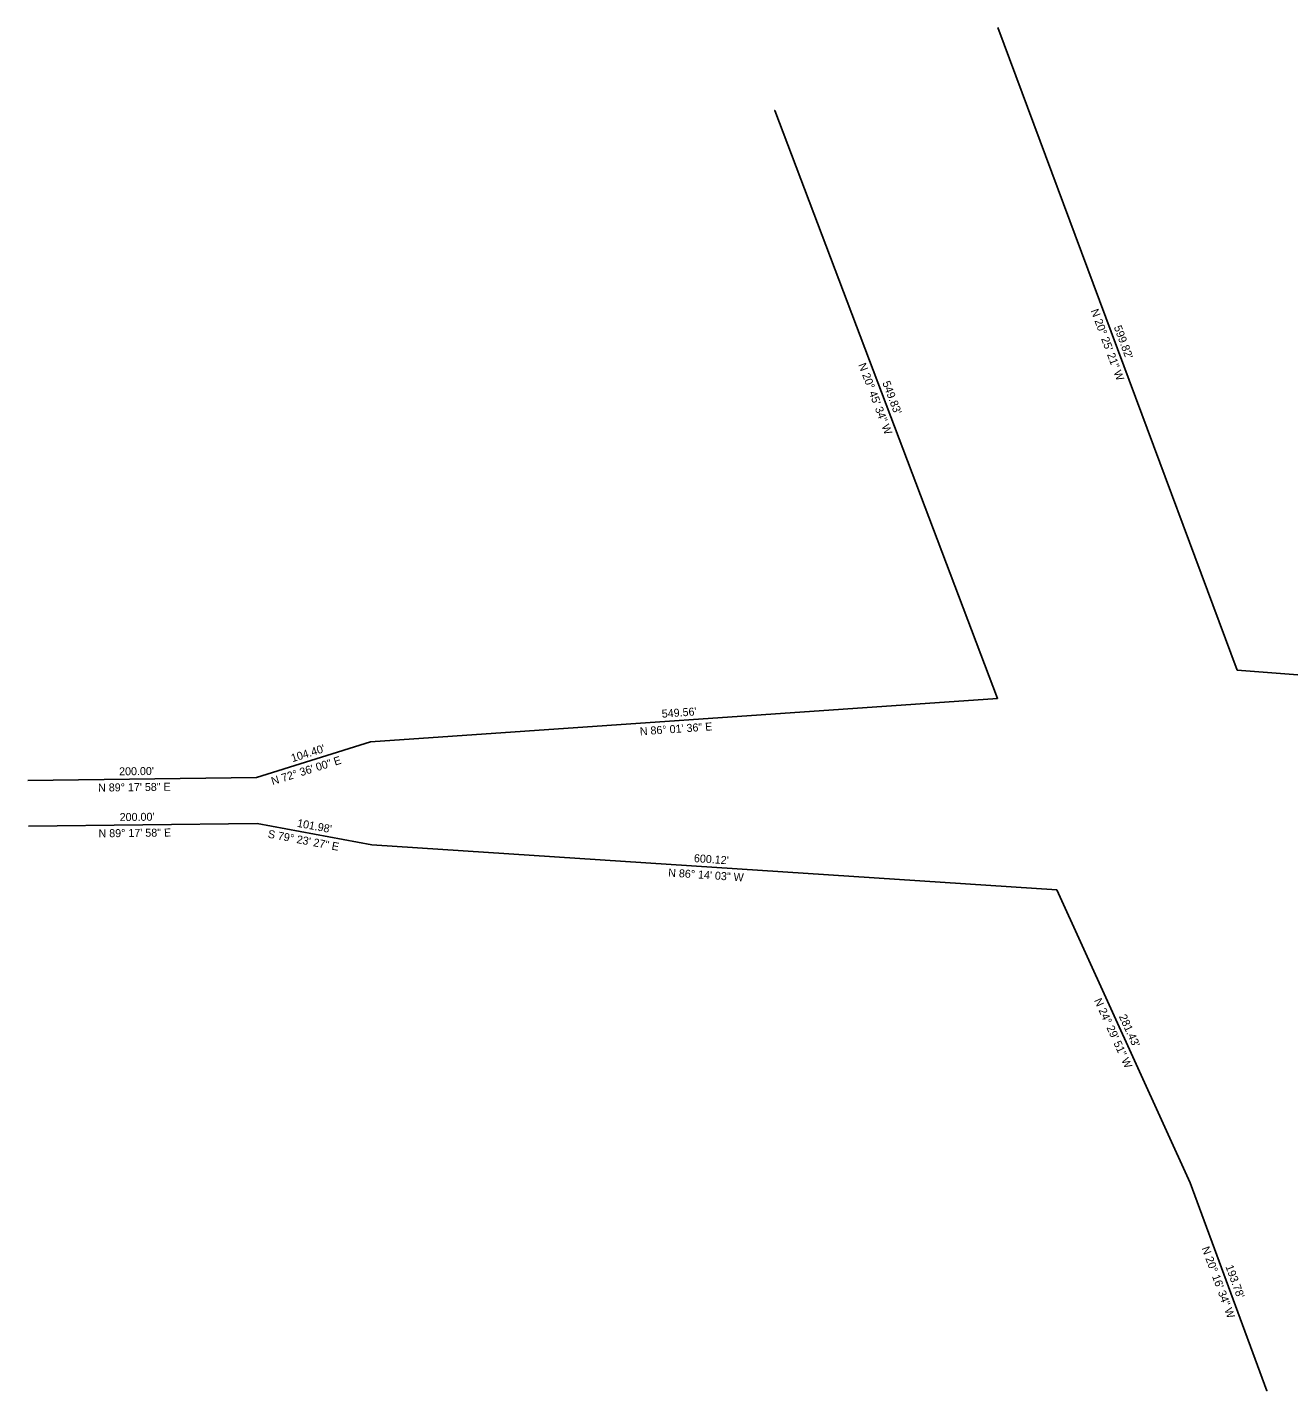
# Model space of a CAD drawing. Extents: x 179269 to 181170, y 300070 to 301262.
# Drawn here: x 179269 to 180372, y 300070 to 301262 of the extents above; entities that cross this region are included whole.
import ezdxf

# ---------------------------------------------------------------- set-up
doc = ezdxf.new("R2010")
doc.units = 0
for name, color, linetype in [('GK_Visualization', 7, 'Continuous'), ('RW_X_Esmt_SH', 7, 'Continuous'), ('RW_X_Fee_WL', 7, 'Continuous'), ('RW_X_Text', 7, 'Continuous')]:
    doc.layers.add(name, color=color, linetype=linetype)

msp = doc.modelspace()

# ---------------------------------------------------------------- linework, layer by layer
at = {"layer": 'GK_Visualization'}
for p, q in [((180117.3, 301261.8), (180117.4, 301261.9)), ((180117.3, 301261.9), (180117.4, 301261.8)), ((180326.6, 300699.8), (180117.3, 301261.9)), ((180326.6, 300699.8), (180117.3, 301261.9)), ((179922.1, 301189.2), (179922.3, 301189.3)), ((179922.1, 301189.3), (179922.3, 301189.2)), ((180117.1, 300675.1), (179922.2, 301189.2)), ((180117.1, 300675.1), (179922.2, 301189.2)), ((180117.1, 300675.1), (179922.2, 301189.2)), ((180326.6, 300699.7), (180326.7, 300699.8)), ((180326.6, 300699.8), (180326.7, 300699.7)), ((180700.4, 300670.3), (180326.6, 300699.8)), ((180700.4, 300670.3), (180326.6, 300699.8)), ((179568.8, 300637), (180117.1, 300675.1)), ((179568.8, 300637), (180117.1, 300675.1)), ((179568.8, 300637), (180117.1, 300675.1)), ((180117, 300675), (180117.1, 300675.2)), ((180117, 300675.2), (180117.1, 300675)), ((179469.2, 300605.8), (179568.8, 300637)), ((179469.2, 300605.8), (179568.8, 300637)), ((179568.8, 300636.9), (179568.9, 300637.1)), ((179568.8, 300637.1), (179568.9, 300636.9)), ((179568.8, 300636.9), (179568.9, 300637.1)), ((179568.8, 300637.1), (179568.9, 300636.9)), ((179269.2, 300603.3), (179469.2, 300605.8)), ((179469.1, 300605.7), (179469.3, 300605.9)), ((179469.1, 300605.9), (179469.3, 300605.7)), ((179269.2, 300603.3), (179269.3, 300603.4)), ((179269.2, 300603.4), (179269.3, 300603.3)), ((179269.6, 300563.3), (179269.8, 300563.4)), ((179269.6, 300563.4), (179269.8, 300563.3)), ((179269.7, 300563.3), (179469.7, 300565.8)), ((179469.6, 300565.7), (179469.8, 300565.9)), ((179469.6, 300565.9), (179469.8, 300565.7)), ((179569.9, 300547), (179469.7, 300565.8)), ((179469.7, 300565.8), (179569.9, 300547)), ((179569.9, 300546.9), (179570, 300547.1)), ((179569.9, 300547.1), (179570, 300546.9)), ((180168.8, 300507.6), (179569.9, 300547)), ((180168.8, 300507.6), (179569.9, 300547)), ((180168.7, 300507.5), (180168.8, 300507.7)), ((180168.7, 300507.7), (180168.8, 300507.5)), ((180285.5, 300251.5), (180168.8, 300507.6)), ((180285.5, 300251.5), (180168.8, 300507.6)), ((180285.4, 300251.4), (180285.5, 300251.6)), ((180285.4, 300251.6), (180285.5, 300251.4)), ((180352.6, 300069.7), (180285.5, 300251.5)), ((180352.6, 300069.7), (180285.5, 300251.5)), ((180352.5, 300069.7), (180352.7, 300069.8)), ((180352.5, 300069.8), (180352.7, 300069.7))]:
    msp.add_line(p, q, dxfattribs=at)
at = {"layer": 'RW_X_Esmt_SH'}
for p, q in [((179469.2, 300605.8), (179568.8, 300637)), ((179269.2, 300603.3), (179469.2, 300605.8)), ((179269.7, 300563.3), (179469.7, 300565.8)), ((179469.7, 300565.8), (179569.9, 300547))]:
    msp.add_line(p, q, dxfattribs=at)
at = {"layer": 'RW_X_Fee_WL'}
for p, q in [((180326.6, 300699.8), (180117.3, 301261.9)), ((180117.1, 300675.1), (179922.2, 301189.2)), ((180700.4, 300670.3), (180326.6, 300699.8)), ((179568.8, 300637), (180117.1, 300675.1)), ((180168.8, 300507.6), (179569.9, 300547)), ((180285.5, 300251.5), (180168.8, 300507.6)), ((180352.6, 300069.7), (180285.5, 300251.5))]:
    msp.add_line(p, q, dxfattribs=at)

# ---------------------------------------------------------------- texts
at = {"layer": 'GK_Visualization'}
for s, p in [('EA712', (180116.8, 301261.9)), ('EA711', (179921.7, 301189.2)), ('EA709', (180326.1, 300699.8)), ('EA710', (180116.5, 300675.1)), ('EA719', (179568.3, 300637)), ('EA719', (179568.3, 300637)), ('EA723', (179468.6, 300605.8)), ('EA726', (179268.7, 300603.3)), ('EA725', (179269.2, 300563.3)), ('EA722', (179469.1, 300565.8)), ('EA721', (179569.4, 300547)), ('EA706', (180168.2, 300507.6)), ('EA705', (180284.9, 300251.5)), ('EA702', (180352, 300069.7))]:
    msp.add_text(s, height=0.14, dxfattribs=at).set_placement(p)
at = {"layer": 'RW_X_Text'}
for s, rotation, p in [('N 20%%d 25\' 21" W', 290.4225, (180198.4, 301014.2)), ("599.82'", 290.4225, (180218.6, 300999.8)), ('N 20%%d 45\' 34" W', 290.7595, (179995.2, 300966.9)), ("549.83'", 290.7595, (180016.2, 300951.2)), ("549.56'", 3.9734, (179823.7, 300658.2)), ('N 86%%d 01\' 36" E', 3.9734, (179804.5, 300642.8)), ("104.40'", 17.3999, (179500.6, 300619.3)), ('N 72%%d 36\' 00" E', 17.3999, (179483.2, 300599.2)), ("200.00'", 0.7007, (179349, 300607.8)), ('N 89%%d 17\' 58" E', 0.7007, (179330.6, 300593.6)), ("200.00'", 0.7007, (179349.5, 300567.8)), ("101.98'", 349.3907, (179504.2, 300562.9)), ('N 89%%d 17\' 58" E', 0.7007, (179331, 300553.6)), ('S 79%%d 23\' 27" E', 349.3907, (179478.6, 300553.4)), ("600.12'", 356.2341, (179851.4, 300532)), ('N 86%%d 14\' 03" W', 356.2341, (179828.9, 300519.4)), ('N 24%%d 29\' 51" W', 294.4976, (180201.3, 300411)), ("281.43'", 294.4976, (180223, 300397)), ('N 20%%d 16\' 34" W', 290.2761, (180295.4, 300194.3)), ("193.78'", 290.2761, (180316.2, 300178.3))]:
    msp.add_text(s, height=7, rotation=rotation, dxfattribs=at).set_placement(p)

doc.saveas('drawing.dxf')
